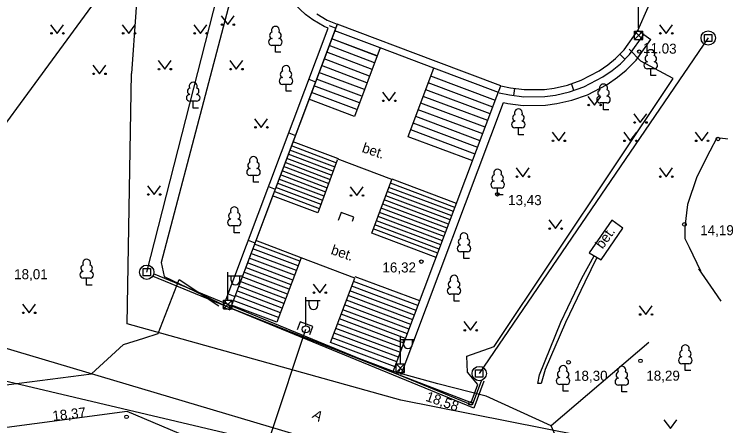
# Model space of a CAD drawing. Extents: x 713497 to 713863, y 6590062 to 6590327.
# Drawn here: x 713659.5 to 713708.83, y 6590277.88 to 6590306.61 of the extents above; entities that cross this region are included whole.
import ezdxf

# ---------------------------------------------------------------- set-up
doc = ezdxf.new("R2010")
doc.units = 0
for name, color, linetype in [('AED', 7, 'Continuous'), ('DKAEV', 7, 'Continuous'), ('HALJASTUS', 7, 'Continuous'), ('HOONE', 7, 'Continuous'), ('HOONEDET', 7, 'Continuous'), ('KORGUS', 7, 'Continuous'), ('KPKAABEL', 7, 'Continuous'), ('MPKAABEL', 7, 'Continuous'), ('POST', 7, 'Continuous'), ('PUU', 7, 'Continuous'), ('SITRASS', 7, 'Continuous'), ('TEE', 7, 'Continuous')]:
    doc.layers.add(name, color=color, linetype=linetype)

msp = doc.modelspace()

# ---------------------------------------------------------------- linework, layer by layer
at = {"layer": 'AED'}
for points in [[(713674.082, 6590286.156), (713681.419, 6590305.636), (713681.135, 6590305.749), (713680.348, 6590306.227), (713679.847, 6590306.599), (713679.073, 6590307.305)], [(713680.628, 6590306.643), (713681.358, 6590306.198), (713682.06, 6590305.92), (713674.55, 6590285.98)], [(713681.484, 6590305.809), (713681.952, 6590305.632)], [(713693.47, 6590301.62), (713694.159, 6590301.464), (713695.1, 6590301.345), (713696.515, 6590301.36), (713697.19, 6590301.449), (713698.117, 6590301.663), (713699.075, 6590302.003), (713700.326, 6590302.656), (713700.943, 6590303.084), (713701.479, 6590303.527), (713702.079, 6590304.119), (713703.04, 6590305.482)], [(713703.449, 6590305.194), (713703.04, 6590305.482)], [(713693.36, 6590301.132), (713694.072, 6590300.971), (713695.071, 6590300.844), (713696.551, 6590300.86), (713697.279, 6590300.957), (713698.257, 6590301.182), (713699.275, 6590301.543), (713700.585, 6590302.227), (713701.246, 6590302.685), (713701.815, 6590303.155), (713702.462, 6590303.794), (713703.449, 6590305.194)], [(713702.132, 6590303.469), (713701.781, 6590303.824)], [(713680.074, 6590302.065), (713680.542, 6590301.889)], [(713698.565, 6590301.291), (713698.398, 6590301.763)], [(713694.387, 6590300.931), (713694.45, 6590301.427)], [(713678.664, 6590298.322), (713679.132, 6590298.146)], [(713677.254, 6590294.579), (713677.722, 6590294.402)], [(713675.844, 6590290.835), (713676.312, 6590290.659)], [(713674.435, 6590287.092), (713674.902, 6590286.916)], [(713674.082, 6590286.156), (713674.55, 6590285.98)]]:
    msp.add_lwpolyline(points, dxfattribs=at)
at = {"layer": 'DKAEV'}
for p, q in [((713707.698, 6590304.701), (713707.698, 6590305.201)), ((713707.698, 6590305.201), (713708.198, 6590305.201)), ((713708.198, 6590305.201), (713708.198, 6590304.701)), ((713708.198, 6590304.701), (713707.698, 6590304.701)), ((713668.509, 6590288.356), (713668.509, 6590288.856)), ((713668.509, 6590288.856), (713669.009, 6590288.856)), ((713669.009, 6590288.856), (713669.009, 6590288.356)), ((713669.009, 6590288.356), (713668.509, 6590288.356)), ((713691.714, 6590281.283), (713691.714, 6590281.783)), ((713691.714, 6590281.783), (713692.214, 6590281.783)), ((713692.214, 6590281.783), (713692.214, 6590281.283)), ((713692.214, 6590281.283), (713691.714, 6590281.283))]:
    msp.add_line(p, q, dxfattribs=at)
for centre in [(713707.948, 6590304.951), (713668.759, 6590288.606), (713691.964, 6590281.533)]:
    msp.add_circle(centre, 0.5, dxfattribs=at)
at = {"layer": 'HALJASTUS'}
for p, q in [((713673.947, 6590306.487), (713674.41, 6590305.88)), ((713674.41, 6590305.88), (713674.856, 6590306.487)), ((713662.047, 6590305.877), (713662.51, 6590305.27)), ((713662.51, 6590305.27), (713662.956, 6590305.877)), ((713667.047, 6590305.877), (713667.51, 6590305.27)), ((713667.51, 6590305.27), (713667.956, 6590305.877)), ((713672.047, 6590305.877), (713672.51, 6590305.27)), ((713672.51, 6590305.27), (713672.956, 6590305.877)), ((713704.547, 6590305.877), (713705.01, 6590305.27)), ((713705.01, 6590305.27), (713705.456, 6590305.877)), ((713664.987, 6590303.057), (713665.45, 6590302.45)), ((713665.45, 6590302.45), (713665.896, 6590303.057)), ((713669.547, 6590303.377), (713670.01, 6590302.77)), ((713670.01, 6590302.77), (713670.456, 6590303.377)), ((713674.547, 6590303.377), (713675.01, 6590302.77)), ((713675.01, 6590302.77), (713675.456, 6590303.377)), ((713685.217, 6590301.167), (713685.68, 6590300.56)), ((713685.68, 6590300.56), (713686.126, 6590301.167)), ((713699.547, 6590300.877), (713700.01, 6590300.27)), ((713700.01, 6590300.27), (713700.456, 6590300.877)), ((713702.747, 6590299.657), (713703.21, 6590299.05)), ((713703.21, 6590299.05), (713703.656, 6590299.657)), ((713676.287, 6590299.317), (713676.75, 6590298.71)), ((713676.75, 6590298.71), (713677.196, 6590299.317)), ((713697.047, 6590298.377), (713697.51, 6590297.77)), ((713697.51, 6590297.77), (713697.956, 6590298.377)), ((713702.047, 6590298.377), (713702.51, 6590297.77)), ((713702.51, 6590297.77), (713702.956, 6590298.377)), ((713707.047, 6590298.377), (713707.51, 6590297.77)), ((713707.51, 6590297.77), (713707.956, 6590298.377)), ((713694.547, 6590295.877), (713695.01, 6590295.27)), ((713695.01, 6590295.27), (713695.456, 6590295.877)), ((713704.547, 6590295.877), (713705.01, 6590295.27)), ((713705.01, 6590295.27), (713705.456, 6590295.877)), ((713668.807, 6590294.637), (713669.27, 6590294.03)), ((713669.27, 6590294.03), (713669.716, 6590294.637)), ((713682.957, 6590294.567), (713683.42, 6590293.96)), ((713683.42, 6590293.96), (713683.866, 6590294.567)), ((713696.827, 6590292.257), (713697.29, 6590291.65)), ((713697.29, 6590291.65), (713697.736, 6590292.257)), ((713680.367, 6590287.777), (713680.83, 6590287.17)), ((713680.83, 6590287.17), (713681.276, 6590287.777)), ((713660.077, 6590286.377), (713660.54, 6590285.77)), ((713660.54, 6590285.77), (713660.986, 6590286.377)), ((713703.137, 6590286.257), (713703.6, 6590285.65)), ((713703.6, 6590285.65), (713704.046, 6590286.257)), ((713690.897, 6590285.157), (713691.36, 6590284.55)), ((713691.36, 6590284.55), (713691.806, 6590285.157)), ((713704.847, 6590278.297), (713705.31, 6590277.69)), ((713705.31, 6590277.69), (713705.756, 6590278.297))]:
    msp.add_line(p, q, dxfattribs=at)
for points in [[(713709.56, 6590297.87), (713708.56, 6590297.99), (713708.07, 6590297.06), (713707.15, 6590295.25), (713706.51, 6590293.33), (713706.31, 6590291.76), (713706.31, 6590290.96), (713706.63, 6590290.35), (713707.4, 6590288.69)], [(713707.27, 6590288.83), (713708.11, 6590287.62), (713708.84, 6590286.58)]]:
    msp.add_lwpolyline(points, dxfattribs=at)
for centre in [(713674.009, 6590305.88), (713674.838, 6590305.88), (713662.109, 6590305.27), (713662.938, 6590305.27), (713667.109, 6590305.27), (713667.938, 6590305.27), (713672.109, 6590305.27), (713672.938, 6590305.27), (713704.609, 6590305.27), (713705.438, 6590305.27), (713665.049, 6590302.45), (713665.878, 6590302.45), (713669.609, 6590302.77), (713670.438, 6590302.77), (713674.609, 6590302.77), (713675.438, 6590302.77), (713685.279, 6590300.56), (713686.108, 6590300.56), (713699.609, 6590300.27), (713700.438, 6590300.27), (713702.809, 6590299.05), (713703.638, 6590299.05), (713676.349, 6590298.71), (713677.178, 6590298.71), (713697.109, 6590297.77), (713697.938, 6590297.77), (713702.109, 6590297.77), (713702.938, 6590297.77), (713707.109, 6590297.77), (713707.938, 6590297.77), (713694.609, 6590295.27), (713695.438, 6590295.27), (713704.609, 6590295.27), (713705.438, 6590295.27), (713668.869, 6590294.03), (713669.698, 6590294.03), (713683.019, 6590293.96), (713683.848, 6590293.96), (713696.889, 6590291.65), (713697.718, 6590291.65), (713680.429, 6590287.17), (713681.258, 6590287.17), (713660.139, 6590285.77), (713660.968, 6590285.77), (713703.199, 6590285.65), (713704.028, 6590285.65), (713690.959, 6590284.55), (713691.788, 6590284.55)]:
    msp.add_circle(centre, 0.055, dxfattribs=at)
at = {"layer": 'HOONE'}
for points in [[(713668.759, 6590288.606), (713675.035, 6590313.217)], [(713707.948, 6590304.951), (713691.964, 6590281.533)], [(713692.288, 6590281.012), (713691.581, 6590279.113), (713669.154, 6590288.33)], [(713692.129, 6590281.071), (713691.483, 6590279.337), (713669.219, 6590288.487)], [(713703.809, 6590283.697), (713696.995, 6590277.895)]]:
    msp.add_lwpolyline(points, dxfattribs=at)
at = {"layer": 'HOONEDET'}
for points in [[(713693.2, 6590300.9), (713693.47, 6590301.62), (713688.97, 6590303.31), (713682.06, 6590305.92), (713681.88, 6590305.45)], [(713681.95, 6590305.41), (713681.88, 6590305.47)], [(713685.05, 6590304.25), (713681.88, 6590305.45)], [(713684.84, 6590303.7), (713681.67, 6590304.9)], [(713684.84, 6590303.69), (713681.67, 6590304.89)], [(713684.49, 6590302.75), (713681.32, 6590303.95)], [(713684.66, 6590303.22), (713681.49, 6590304.42)], [(713684.31, 6590302.29), (713681.14, 6590303.49)], [(713684.13, 6590301.82), (713680.96, 6590303.02)], [(713683.95, 6590301.35), (713680.78, 6590302.55)], [(713693.3, 6590301.15), (713688.79, 6590302.84)], [(713683.78, 6590300.88), (713680.61, 6590302.08)], [(713693.09, 6590300.59), (713688.58, 6590302.28)], [(713683.6, 6590300.42), (713680.43, 6590301.62)], [(713692.91, 6590300.12), (713688.4, 6590301.81)], [(713683.42, 6590299.95), (713680.25, 6590301.15)], [(713692.74, 6590299.65), (713688.23, 6590301.34)], [(713683.25, 6590299.48), (713680.08, 6590300.68)], [(713692.56, 6590299.18), (713688.05, 6590300.87)], [(713692.39, 6590298.72), (713687.88, 6590300.41)], [(713692.21, 6590298.25), (713687.7, 6590299.94)], [(713692.04, 6590297.78), (713687.53, 6590299.47)], [(713691.69, 6590296.84), (713687.18, 6590298.53)], [(713691.86, 6590297.31), (713687.35, 6590299)], [(713691.51, 6590296.37), (713687, 6590298.06)], [(713682.14, 6590296.51), (713678.97, 6590297.71)], [(713681.92, 6590295.93), (713678.75, 6590297.13)], [(713682.03, 6590296.22), (713678.86, 6590297.42)], [(713681.7, 6590295.35), (713678.53, 6590296.55)], [(713681.81, 6590295.64), (713678.64, 6590296.84)], [(713681.59, 6590295.06), (713678.42, 6590296.26)], [(713681.37, 6590294.48), (713678.2, 6590295.68)], [(713681.48, 6590294.77), (713678.31, 6590295.97)], [(713681.15, 6590293.9), (713677.98, 6590295.1)], [(713681.26, 6590294.19), (713678.09, 6590295.39)], [(713690.38, 6590293.41), (713685.88, 6590295.1)], [(713681.04, 6590293.61), (713677.87, 6590294.81)], [(713690.27, 6590293.12), (713685.77, 6590294.81)], [(713680.82, 6590293.03), (713677.65, 6590294.23)], [(713680.93, 6590293.32), (713677.76, 6590294.52)], [(713690.05, 6590292.54), (713685.55, 6590294.23)], [(713690.16, 6590292.83), (713685.66, 6590294.52)], [(713680.71, 6590292.74), (713677.54, 6590293.94)], [(713689.83, 6590291.96), (713685.33, 6590293.65)], [(713689.94, 6590292.25), (713685.44, 6590293.94)], [(713689.73, 6590291.67), (713685.23, 6590293.36)], [(713683.11, 6590292.16), (713683.22, 6590292.44), (713682.33, 6590292.78), (713682.12, 6590292.21)], [(713689.51, 6590291.09), (713685.01, 6590292.78)], [(713689.62, 6590291.38), (713685.12, 6590293.07)], [(713689.29, 6590290.51), (713684.79, 6590292.2)], [(713689.4, 6590290.8), (713684.9, 6590292.49)], [(713689.07, 6590289.93), (713684.57, 6590291.62)], [(713689.18, 6590290.22), (713684.68, 6590291.91)], [(713688.96, 6590289.64), (713684.46, 6590291.33)], [(713679.54, 6590289.61), (713676.37, 6590290.81)], [(713679.33, 6590289.04), (713676.16, 6590290.24)], [(713679.45, 6590289.37), (713676.28, 6590290.57)], [(713679.2, 6590288.72), (713676.03, 6590289.92)], [(713678.95, 6590288.06), (713675.78, 6590289.26)], [(713679.08, 6590288.39), (713675.91, 6590289.59)], [(713678.83, 6590287.73), (713675.66, 6590288.93)], [(713678.58, 6590287.08), (713675.41, 6590288.28)], [(713678.71, 6590287.41), (713675.54, 6590288.61)], [(713687.81, 6590286.6), (713683.31, 6590288.29)], [(713678.46, 6590286.75), (713675.29, 6590287.95)], [(713687.69, 6590286.27), (713683.19, 6590287.96)], [(713678.21, 6590286.1), (713675.04, 6590287.3)], [(713678.33, 6590286.42), (713675.16, 6590287.62)], [(713687.44, 6590285.61), (713682.94, 6590287.3)], [(713687.57, 6590285.94), (713683.07, 6590287.63)], [(713678.09, 6590285.77), (713674.92, 6590286.97)], [(713687.32, 6590285.29), (713682.82, 6590286.98)], [(713677.84, 6590285.11), (713674.67, 6590286.31)], [(713677.96, 6590285.44), (713674.79, 6590286.64)], [(713687.07, 6590284.63), (713682.57, 6590286.32)], [(713687.2, 6590284.96), (713682.7, 6590286.65)], [(713686.95, 6590284.3), (713682.45, 6590285.99)], [(713686.71, 6590283.65), (713682.21, 6590285.34)], [(713686.83, 6590283.98), (713682.33, 6590285.67)], [(713680.13, 6590284.25), (713680.35, 6590284.81), (713679.46, 6590285.15), (713679.25, 6590284.59)], [(713686.58, 6590283.32), (713682.08, 6590285.01)], [(713686.34, 6590282.67), (713681.84, 6590284.36)], [(713686.46, 6590282.99), (713681.96, 6590284.68)], [(713686.21, 6590282.34), (713681.71, 6590284.03)], [(713685.97, 6590281.68), (713681.47, 6590283.37)], [(713686.09, 6590282.01), (713681.59, 6590283.7)]]:
    msp.add_lwpolyline(points, dxfattribs=at)
at = {"layer": 'KORGUS'}
for centre, radius in [((713703.135, 6590304.004), 0.117), ((713708.63, 6590297.9), 0.125), ((713693.23, 6590294.04), 0.125), ((713706.29, 6590291.94), 0.125), ((713687.92, 6590289.34), 0.125), ((713698.2, 6590282.32), 0.125), ((713703.22, 6590282.42), 0.125), ((713691.35, 6590279.45), 0.125), ((713667.35, 6590278.51), 0.125)]:
    msp.add_circle(centre, radius, dxfattribs=at)
at = {"layer": 'KPKAABEL'}
for points in [[(713629.456, 6590327.391), (713641.981, 6590325.582), (713651.254, 6590324.459), (713665.51, 6590322.099), (713668.075, 6590321.478), (713668.718, 6590320.512), (713668.939, 6590319.317), (713668.609, 6590315.326), (713667.69, 6590302.48)], [(713706.45, 6590275.72), (713686.49, 6590279.67), (713667.39, 6590285), (713667.69, 6590302.48)]]:
    msp.add_lwpolyline(points, dxfattribs=at)
at = {"layer": 'MPKAABEL'}
for points in [[(713676.139, 6590313.504), (713669.772, 6590289.28), (713669.97, 6590288.316), (713674.295, 6590286.234)], [(713686.464, 6590281.909), (713686.253, 6590281.48), (713691.391, 6590279.507), (713691.859, 6590280.759), (713691.137, 6590281.629), (713691.093, 6590282.753), (713693.006, 6590283.412), (713705.508, 6590302.133), (713703.246, 6590303.337), (713702.436, 6590304.18)], [(713598.37, 6590297.57), (713604.09, 6590296.01), (713644.48, 6590284.41), (713684.62, 6590274.96), (713706.75, 6590268.92)], [(713674.422, 6590286.344), (713674.295, 6590286.234), (713686.253, 6590281.48)], [(713679.406, 6590249.131), (713681.25, 6590252.91), (713685.54, 6590261.97), (713683.24, 6590270.58), (713677.82, 6590272.99), (713677.47, 6590277.42), (713679.86, 6590284.62)]]:
    msp.add_lwpolyline(points, dxfattribs=at)
at = {"layer": 'POST'}
for p, q in [((713703.081, 6590305.651), (713703.081, 6590307.651)), ((713703.396, 6590305.436), (713702.796, 6590304.836)), ((713703.396, 6590304.836), (713702.796, 6590305.436)), ((713702.796, 6590305.436), (713703.396, 6590305.436)), ((713702.796, 6590304.836), (713702.796, 6590305.436)), ((713703.396, 6590304.836), (713703.396, 6590305.436)), ((713702.796, 6590304.836), (713703.396, 6590304.836)), ((713674.413, 6590286.602), (713674.413, 6590288.602)), ((713674.413, 6590288.352), (713675.413, 6590288.352)), ((713674.64, 6590288.031), (713674.64, 6590288.352)), ((713675.252, 6590288.031), (713675.252, 6590288.352)), ((713679.86, 6590284.87), (713679.86, 6590286.87)), ((713674.713, 6590286.652), (713674.113, 6590286.052)), ((713674.713, 6590286.052), (713674.113, 6590286.652)), ((713674.113, 6590286.652), (713674.713, 6590286.652)), ((713674.113, 6590286.052), (713674.113, 6590286.652)), ((713674.713, 6590286.052), (713674.713, 6590286.652)), ((713679.86, 6590286.62), (713680.86, 6590286.62)), ((713680.087, 6590286.299), (713680.087, 6590286.62)), ((713680.699, 6590286.299), (713680.699, 6590286.62)), ((713674.113, 6590286.052), (713674.713, 6590286.052)), ((713686.46, 6590282.154), (713686.46, 6590284.154)), ((713686.46, 6590283.904), (713687.46, 6590283.904)), ((713686.687, 6590283.583), (713686.687, 6590283.904)), ((713687.299, 6590283.583), (713687.299, 6590283.904)), ((713686.76, 6590282.204), (713686.16, 6590281.604)), ((713686.76, 6590281.604), (713686.16, 6590282.204)), ((713686.16, 6590282.204), (713686.76, 6590282.204)), ((713686.16, 6590281.604), (713686.16, 6590282.204)), ((713686.76, 6590281.604), (713686.76, 6590282.204)), ((713686.16, 6590281.604), (713686.76, 6590281.604))]:
    msp.add_line(p, q, dxfattribs=at)
msp.add_circle((713679.86, 6590284.62), 0.25, dxfattribs=at)
for centre in [(713674.946, 6590288.031), (713680.393, 6590286.299), (713686.993, 6590283.583)]:
    msp.add_arc(centre, 0.306, 180, 0, dxfattribs=at)
at = {"layer": 'PUU'}
for p, q in [((713677.98, 6590304.435), (713677.5, 6590304.435)), ((713677.74, 6590303.96), (713677.74, 6590304.435)), ((713678.12, 6590303.96), (713677.74, 6590303.96)), ((713704.18, 6590302.805), (713703.7, 6590302.805)), ((713703.94, 6590302.33), (713703.94, 6590302.805)), ((713704.32, 6590302.33), (713703.94, 6590302.33)), ((713678.72, 6590301.705), (713678.24, 6590301.705)), ((713678.48, 6590301.23), (713678.48, 6590301.705)), ((713678.86, 6590301.23), (713678.48, 6590301.23)), ((713672.24, 6590300.535), (713671.76, 6590300.535)), ((713672, 6590300.06), (713672, 6590300.535)), ((713672.38, 6590300.06), (713672, 6590300.06)), ((713700.88, 6590300.415), (713700.4, 6590300.415)), ((713700.64, 6590299.94), (713700.64, 6590300.415)), ((713701.02, 6590299.94), (713700.64, 6590299.94)), ((713694.94, 6590298.675), (713694.46, 6590298.675)), ((713694.7, 6590298.2), (713694.7, 6590298.675)), ((713695.08, 6590298.2), (713694.7, 6590298.2)), ((713676.45, 6590295.355), (713675.97, 6590295.355)), ((713676.21, 6590294.88), (713676.21, 6590295.355)), ((713676.59, 6590294.88), (713676.21, 6590294.88)), ((713693.49, 6590294.475), (713693.01, 6590294.475)), ((713693.25, 6590294), (713693.25, 6590294.475)), ((713693.63, 6590294), (713693.25, 6590294)), ((713675.11, 6590291.835), (713674.63, 6590291.835)), ((713674.87, 6590291.36), (713674.87, 6590291.835)), ((713675.25, 6590291.36), (713674.87, 6590291.36)), ((713691.14, 6590290.025), (713690.66, 6590290.025)), ((713690.9, 6590289.55), (713690.9, 6590290.025)), ((713691.28, 6590289.55), (713690.9, 6590289.55)), ((713664.8, 6590288.185), (713664.32, 6590288.185)), ((713664.56, 6590287.71), (713664.56, 6590288.185)), ((713664.94, 6590287.71), (713664.56, 6590287.71)), ((713690.45, 6590287.065), (713689.97, 6590287.065)), ((713690.21, 6590286.59), (713690.21, 6590287.065)), ((713690.59, 6590286.59), (713690.21, 6590286.59)), ((713706.59, 6590282.215), (713706.11, 6590282.215)), ((713706.35, 6590281.74), (713706.35, 6590282.215)), ((713706.73, 6590281.74), (713706.35, 6590281.74)), ((713698.06, 6590280.775), (713697.58, 6590280.775)), ((713697.82, 6590280.3), (713697.82, 6590280.775)), ((713698.2, 6590280.3), (713697.82, 6590280.3)), ((713702.16, 6590280.725), (713701.68, 6590280.725)), ((713701.92, 6590280.25), (713701.92, 6590280.725)), ((713702.3, 6590280.25), (713701.92, 6590280.25))]:
    msp.add_line(p, q, dxfattribs=at)
for centre, radius, start, end in [((713677.74, 6590305.48), 0.277, 332.5799, 207.4201), ((713677.57, 6590305.133), 0.233, 109.0217, 253.1415), ((713677.91, 6590305.133), 0.233, 286.8508, 70.9859), ((713677.503, 6590304.672), 0.238, 90.0016, 269.3953), ((713677.977, 6590304.672), 0.238, 270.6047, 89.9984), ((713703.94, 6590303.85), 0.277, 332.5799, 207.4201), ((713703.77, 6590303.503), 0.233, 109.0217, 253.1415), ((713704.11, 6590303.503), 0.233, 286.8508, 70.9859), ((713678.48, 6590302.75), 0.277, 332.5799, 207.4201), ((713703.703, 6590303.042), 0.238, 90.0016, 269.3953), ((713704.177, 6590303.042), 0.238, 270.6047, 89.9984), ((713678.31, 6590302.403), 0.233, 109.0217, 253.1415), ((713678.65, 6590302.403), 0.233, 286.8508, 70.9859), ((713678.243, 6590301.942), 0.238, 90.0016, 269.3953), ((713678.717, 6590301.942), 0.238, 270.6047, 89.9984), ((713672, 6590301.58), 0.277, 332.5799, 207.4201), ((713700.64, 6590301.46), 0.277, 332.5799, 207.4201), ((713671.763, 6590300.772), 0.238, 90.0016, 269.3953), ((713671.83, 6590301.233), 0.233, 109.0217, 253.1415), ((713672.17, 6590301.233), 0.233, 286.8508, 70.9859), ((713672.237, 6590300.772), 0.238, 270.6047, 89.9984), ((713700.47, 6590301.113), 0.233, 109.0217, 253.1415), ((713700.81, 6590301.113), 0.233, 286.8508, 70.9859), ((713700.403, 6590300.652), 0.238, 90.0016, 269.3953), ((713700.877, 6590300.652), 0.238, 270.6047, 89.9984), ((713694.7, 6590299.72), 0.277, 332.5799, 207.4201), ((713694.53, 6590299.373), 0.233, 109.0217, 253.1415), ((713694.87, 6590299.373), 0.233, 286.8508, 70.9859), ((713694.463, 6590298.912), 0.238, 90.0016, 269.3953), ((713694.937, 6590298.912), 0.238, 270.6047, 89.9984), ((713676.21, 6590296.4), 0.277, 332.5799, 207.4201), ((713676.04, 6590296.053), 0.233, 109.0217, 253.1415), ((713676.38, 6590296.053), 0.233, 286.8508, 70.9859), ((713675.973, 6590295.592), 0.238, 90.0016, 269.3953), ((713676.447, 6590295.592), 0.238, 270.6047, 89.9984), ((713693.25, 6590295.52), 0.277, 332.5799, 207.4201), ((713693.08, 6590295.173), 0.233, 109.0217, 253.1415), ((713693.42, 6590295.173), 0.233, 286.8508, 70.9859), ((713693.013, 6590294.712), 0.238, 90.0016, 269.3953), ((713693.487, 6590294.712), 0.238, 270.6047, 89.9984), ((713674.87, 6590292.88), 0.277, 332.5799, 207.4201), ((713674.7, 6590292.533), 0.233, 109.0217, 253.1415), ((713675.04, 6590292.533), 0.233, 286.8508, 70.9859), ((713674.633, 6590292.072), 0.238, 90.0016, 269.3953), ((713675.107, 6590292.072), 0.238, 270.6047, 89.9984), ((713690.9, 6590291.07), 0.277, 332.5799, 207.4201), ((713690.73, 6590290.723), 0.233, 109.0217, 253.1415), ((713691.07, 6590290.723), 0.233, 286.8508, 70.9859), ((713690.663, 6590290.262), 0.238, 90.0016, 269.3953), ((713691.137, 6590290.262), 0.238, 270.6047, 89.9984), ((713664.56, 6590289.23), 0.277, 332.5799, 207.4201), ((713664.323, 6590288.422), 0.238, 90.0016, 269.3953), ((713664.39, 6590288.883), 0.233, 109.0217, 253.1415), ((713664.73, 6590288.883), 0.233, 286.8508, 70.9859), ((713664.797, 6590288.422), 0.238, 270.6047, 89.9984), ((713690.21, 6590288.11), 0.277, 332.5799, 207.4201), ((713690.04, 6590287.763), 0.233, 109.0217, 253.1415), ((713690.38, 6590287.763), 0.233, 286.8508, 70.9859), ((713689.973, 6590287.302), 0.238, 90.0016, 269.3953), ((713690.447, 6590287.302), 0.238, 270.6047, 89.9984), ((713706.35, 6590283.26), 0.277, 332.5799, 207.4201), ((713706.18, 6590282.913), 0.233, 109.0217, 253.1415), ((713706.52, 6590282.913), 0.233, 286.8508, 70.9859), ((713706.113, 6590282.452), 0.238, 90.0016, 269.3953), ((713706.587, 6590282.452), 0.238, 270.6047, 89.9984), ((713697.82, 6590281.82), 0.277, 332.5799, 207.4201), ((713701.92, 6590281.77), 0.277, 332.5799, 207.4201), ((713697.583, 6590281.012), 0.238, 90.0016, 269.3953), ((713697.65, 6590281.473), 0.233, 109.0217, 253.1415), ((713697.99, 6590281.473), 0.233, 286.8508, 70.9859), ((713698.057, 6590281.012), 0.238, 270.6047, 89.9984), ((713701.75, 6590281.423), 0.233, 109.0217, 253.1415), ((713702.09, 6590281.423), 0.233, 286.8508, 70.9859), ((713701.683, 6590280.962), 0.238, 90.0016, 269.3953), ((713702.157, 6590280.962), 0.238, 270.6047, 89.9984)]:
    msp.add_arc(centre, radius, start, end, dxfattribs=at)
at = {"layer": 'SITRASS'}
for points in [[(713677.213, 6590327.391), (713672.58, 6590318.81), (713670.376, 6590315.097), (713670.366, 6590315.08), (713668.84, 6590312.51), (713666.62, 6590309.54), (713652.24, 6590289.93), (713650.28, 6590287.06), (713649.69, 6590286.04)], [(713649.69, 6590286.04), (713683.16, 6590276.09), (713706.71, 6590269.85)]]:
    msp.add_lwpolyline(points, dxfattribs=at)
at = {"layer": 'TEE'}
for points in [[(713703.04, 6590305.482), (713703.764, 6590307.109), (713704.592, 6590308.787), (713704.997, 6590309.632)], [(713681.88, 6590305.45), (713674.55, 6590285.98)], [(713703.449, 6590305.194), (713703.939, 6590304.848)], [(713693.67, 6590300.447), (713693.968, 6590300.38), (713695.036, 6590300.244), (713696.594, 6590300.261), (713697.387, 6590300.366), (713698.425, 6590300.605), (713699.516, 6590300.992), (713700.897, 6590301.713), (713701.608, 6590302.207), (713702.217, 6590302.71), (713702.921, 6590303.405), (713703.939, 6590304.848)], [(713687, 6590298.07), (713688.8, 6590302.84), (713685.05, 6590304.25), (713683.25, 6590299.48)], [(713685.96, 6590281.68), (713693.2, 6590300.9)], [(713686.521, 6590281.468), (713693.67, 6590300.447)], [(713682.06, 6590296.43), (713680.71, 6590292.74)], [(713684.46, 6590291.33), (713685.87, 6590295.08), (713682.04, 6590296.52)], [(713699.63, 6590289.95), (713700.48, 6590289.46), (713701.98, 6590291.68), (713701.22, 6590292.23), (713699.63, 6590289.95)], [(713700.17, 6590289.64), (713699.34, 6590287.9), (713697.98, 6590285.09), (713696.57, 6590281.82), (713696.28, 6590280.84), (713696.05, 6590280.84), (713696.18, 6590281.45), (713697.66, 6590285.11), (713699.12, 6590288.18), (713699.98, 6590289.75)], [(713681.59, 6590283.71), (713683.28, 6590288.2), (713679.53, 6590289.61), (713677.84, 6590285.12)], [(713647.189, 6590279.23), (713656.219, 6590280.395), (713664.901, 6590281.515), (713666.295, 6590282.797), (713667.136, 6590283.569), (713668.544, 6590284.012), (713669.556, 6590284.33), (713671.03, 6590288.101), (713673.8, 6590286.26)], [(713705.99, 6590269.548), (713701.493, 6590267.478), (713699.784, 6590271.456), (713697.868, 6590275.915), (713696.995, 6590277.895), (713692.44, 6590279.952), (713689.087, 6590280.81), (713685.96, 6590281.68)], [(713670.756, 6590228.07), (713675.837, 6590238.63), (713677.485, 6590242.372), (713678.628, 6590244.86), (713679.38, 6590246.468), (713680.165, 6590248.022), (713684.931, 6590257.984), (713686.58, 6590261.37), (713684.169, 6590271.801), (713667.396, 6590278.873), (713647.964, 6590276.295)]]:
    msp.add_lwpolyline(points, dxfattribs=at)

# ---------------------------------------------------------------- texts
at = {"layer": 'KORGUS'}
for s, rotation, p in [('11.03', 358.3884, (713703.39, 6590303.91)), ('18,58', 341.063, (713688.177, 6590279.641)), ('18,37', 6.4729, (713662.218, 6590278.223))]:
    msp.add_text(s, height=0.7, rotation=rotation, dxfattribs=at).set_placement(p)
for s, p in [('13,43', (713693.981, 6590293.285)), ('14,19', (713707.391, 6590291.185)), ('16,32', (713685.208, 6590288.585)), ('18,01', (713659.502, 6590288.115)), ('18,29', (713703.626, 6590281.035)), ('18,30', (713698.581, 6590281.025))]:
    msp.add_text(s, height=0.7, dxfattribs=at).set_placement(p)
at = {"layer": 'TEE'}
for s, rotation, p in [('bet.', 341.4754, (713683.732, 6590297)), ('bet.', 54.1651, (713700.574, 6590290.18)), ('bet.', 341.4754, (713681.562, 6590289.88)), ('A', 327.1011, (713680.252, 6590278.483))]:
    msp.add_text(s, height=0.7, rotation=rotation, dxfattribs=at).set_placement(p)

doc.saveas('drawing.dxf')
